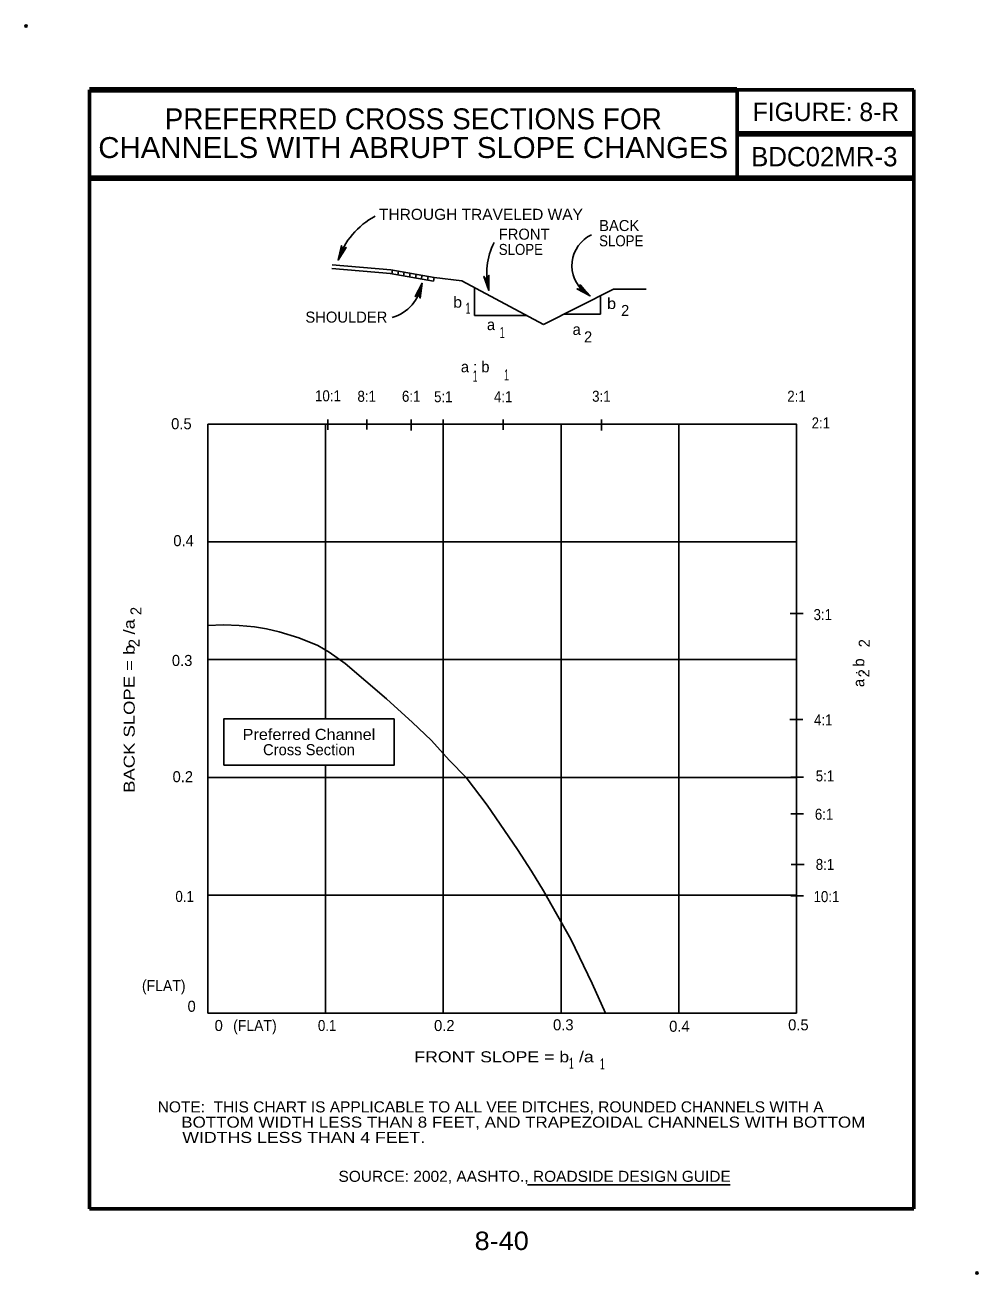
# Model space of a CAD drawing. Extents: x 11.814 to 12.489, y 6.004 to 6.888.
import ezdxf
from ezdxf.enums import TextEntityAlignment as Align

# ---------------------------------------------------------------- set-up
doc = ezdxf.new("R2010")
doc.units = 0
doc.header["$LTSCALE"] = 0.0031
doc.header["$PDMODE"] = 32
doc.header["$PDSIZE"] = 0.00155
doc.layers.add('1', color=7, linetype='Continuous', lineweight=25)
doc.layers.add('24', color=7, linetype='Continuous', lineweight=25)

msp = doc.modelspace()

# ---------------------------------------------------------------- linework, layer by layer
at = {"layer": '1', "lineweight": 60}
for p, q in [((12.443558, 6.842075), (11.859992, 6.842075)), ((11.859992, 6.842075), (11.859992, 6.050092)), ((12.318508, 6.77955), (12.318508, 6.842075)), ((12.443558, 6.050092), (12.443558, 6.842075)), ((12.443558, 6.810817), (12.318508, 6.810817)), ((12.443558, 6.77955), (11.859992, 6.77955)), ((11.859992, 6.050092), (12.443558, 6.050092))]:
    msp.add_line(p, q, dxfattribs=at)
at = {"layer": '1', "lineweight": 90}
for p, q in [((11.859992, 6.842075), (12.318283, 6.842075)), ((12.318575, 6.810833), (12.443558, 6.810833)), ((11.859992, 6.779583), (12.443267, 6.779583))]:
    msp.add_line(p, q, dxfattribs=at)
at = {"layer": '1'}
for p, q in [((12.072992, 6.71195), (12.031467, 6.715592)), ((12.10355, 6.70655), (12.072767, 6.711983)), ((12.073925, 6.711825), (12.074383, 6.7144)), ((12.07815, 6.711075), (12.078608, 6.71365)), ((12.082175, 6.710358), (12.082633, 6.712933)), ((12.086483, 6.709583), (12.086942, 6.712158)), ((12.090742, 6.708825), (12.0912, 6.7114)), ((12.094875, 6.7081), (12.095333, 6.710667)), ((12.099267, 6.707317), (12.099725, 6.709892)), ((12.10355, 6.70655), (12.104008, 6.709125)), ((12.132583, 6.68235), (12.132583, 6.701575)), ((12.231058, 6.700925), (12.181258, 6.676033)), ((12.214333, 6.696117), (12.210717, 6.698633)), ((12.221742, 6.683242), (12.221742, 6.696267)), ((12.231058, 6.700925), (12.254183, 6.700925)), ((12.132583, 6.68235), (12.169058, 6.68235)), ((12.195692, 6.683242), (12.221742, 6.683242)), ((11.943692, 6.60545), (11.943692, 6.188617)), ((12.027058, 6.60545), (12.027058, 6.396808)), ((12.02875, 6.601275), (12.02875, 6.608775)), ((12.056175, 6.601583), (12.056175, 6.608775)), ((12.087667, 6.600958), (12.087667, 6.608775)), ((12.110425, 6.60065), (12.110425, 6.608775)), ((12.110425, 6.60545), (12.110425, 6.188617)), ((12.152817, 6.601275), (12.152817, 6.608775)), ((12.193792, 6.60545), (12.193792, 6.188617)), ((12.22235, 6.600958), (12.22235, 6.608775)), ((12.277158, 6.60545), (12.277158, 6.188617)), ((11.943692, 6.522083), (12.360525, 6.522083)), ((12.356142, 6.4713), (12.365225, 6.4713)), ((11.943692, 6.438717), (12.360525, 6.438717)), ((12.355825, 6.396458), (12.364917, 6.396458)), ((12.027058, 6.364), (12.027058, 6.188617)), ((11.943692, 6.35535), (12.360525, 6.35535)), ((12.35645, 6.355608), (12.365542, 6.355608)), ((12.35645, 6.329483), (12.365542, 6.329483)), ((12.356767, 6.293625), (12.36585, 6.293625)), ((11.943692, 6.271983), (12.360525, 6.271983)), ((12.35645, 6.271483), (12.365542, 6.271483)), ((11.943692, 6.188617), (12.360525, 6.188617)), ((12.17015, 6.067), (12.313483, 6.067))]:
    msp.add_line(p, q, dxfattribs=at)
for points in [[(12.104008, 6.709125), (12.073225, 6.714558), (12.0317, 6.718192)], [(12.104008, 6.709125), (12.123442, 6.7068), (12.181258, 6.676033)], [(11.943692, 6.60545), (12.360525, 6.60545), (12.360525, 6.188617)]]:
    msp.add_lwpolyline(points, dxfattribs=at)
for points in [[(11.943692, 6.188617), (11.943617, 6.462825), (11.954808, 6.463342), (11.965867, 6.462875), (11.976767, 6.461875), (11.985158, 6.460417), (11.9942, 6.45845), (12.008017, 6.454275), (12.021642, 6.44875), (12.0297, 6.444092), (12.041008, 6.435925), (12.070267, 6.410967), (12.088725, 6.394267), (12.10185, 6.381633), (12.114875, 6.367383), (12.126567, 6.355392), (12.141583, 6.33575), (12.163058, 6.304242), (12.172858, 6.288925), (12.181358, 6.275033), (12.200683, 6.240783), (12.215875, 6.209442), (12.225342, 6.188608)], [(11.943692, 6.188617), (11.943617, 6.462825), (11.954808, 6.463342), (11.965867, 6.462875), (11.976767, 6.461875), (11.985158, 6.460417), (11.9942, 6.45845), (12.008017, 6.454275), (12.021642, 6.44875), (12.0297, 6.444092), (12.041008, 6.435925), (12.070267, 6.410967), (12.088725, 6.394267), (12.10185, 6.381633), (12.114875, 6.367383), (12.126567, 6.355392), (12.141583, 6.33575), (12.163058, 6.304242), (12.172858, 6.288925), (12.181358, 6.275033), (12.200683, 6.240783), (12.215875, 6.209442), (12.225342, 6.188608)], [(11.943692, 6.188617), (11.943617, 6.462825), (11.954808, 6.463342), (11.965867, 6.462875), (11.976767, 6.461875), (11.985158, 6.460417), (11.9942, 6.45845), (12.008017, 6.454275), (12.021642, 6.44875), (12.0297, 6.444092), (12.041008, 6.435925), (12.070267, 6.410967), (12.088725, 6.394267), (12.10185, 6.381633), (12.114875, 6.367383), (12.126567, 6.355392), (12.141583, 6.33575), (12.163058, 6.304242), (12.172858, 6.288925), (12.181358, 6.275033), (12.200683, 6.240783), (12.215875, 6.209442), (12.225342, 6.188608)], [(11.955, 6.364), (12.075583, 6.364), (12.075583, 6.396808), (11.955, 6.396808)], [(11.955, 6.364), (12.075583, 6.364), (12.075583, 6.396808), (11.955, 6.396808)], [(11.955, 6.364), (12.075583, 6.364), (12.075583, 6.396808), (11.955, 6.396808)]]:
    msp.add_lwpolyline(points, close=True, dxfattribs=at)
for centre, radius, start, end in [((12.086862, 6.705027), 0.053529, 117.42279, 162.04065), ((12.22559, 6.717598), 0.0241, 115.10644, 231.89061), ((12.189346, 6.712244), 0.048143, 153.1592, 194.61624), ((12.065787, 6.709473), 0.029882, 286.38176, 351.53669)]:
    msp.add_arc(centre, radius, start, end, dxfattribs=at)
for p in [(11.814967, 6.88715), (12.151633, 6.842075), (12.4883, 6.00465)]:
    msp.add_point(p, dxfattribs=at)
at = {"layer": '24'}
for points in [[(12.035942, 6.721533), (12.041633, 6.730433), (12.038983, 6.728842), (12.038242, 6.731783), (12.035942, 6.721533), (12.036192, 6.722183), (12.041392, 6.730217), (12.038883, 6.728675), (12.038217, 6.731342), (12.036308, 6.722533), (12.036483, 6.722833), (12.0409, 6.729733), (12.038867, 6.728625), (12.038275, 6.730883), (12.03655, 6.722983), (12.036633, 6.723325), (12.040508, 6.729342), (12.038858, 6.728542), (12.038225, 6.730325), (12.037017, 6.72425), (12.037242, 6.724792), (12.040067, 6.728958), (12.038842, 6.728433), (12.038283, 6.729783), (12.037333, 6.724867), (12.037575, 6.725367), (12.039583, 6.72855), (12.038642, 6.728167), (12.038283, 6.729158), (12.037742, 6.72585), (12.037983, 6.726317), (12.039233, 6.728208), (12.038633, 6.728067), (12.03835, 6.728833), (12.038042, 6.726583), (12.038917, 6.727792), (12.038475, 6.72775), (12.03835, 6.728492), (12.038133, 6.726942), (12.038725, 6.727733), (12.038275, 6.727483), (12.038283, 6.727983), (12.038375, 6.72745), (12.038517, 6.72765)], [(12.142758, 6.700092), (12.142758, 6.71065), (12.141383, 6.707883), (12.139175, 6.709958), (12.142758, 6.700092), (12.142617, 6.700775), (12.142675, 6.710342), (12.141392, 6.707692), (12.139383, 6.709575), (12.142525, 6.701133), (12.142517, 6.701483), (12.142517, 6.709675), (12.141408, 6.707642), (12.139692, 6.709225), (12.142492, 6.701642), (12.142375, 6.701967), (12.1424, 6.709133), (12.141442, 6.707567), (12.139942, 6.708725), (12.1422, 6.70295), (12.1421, 6.703542), (12.142233, 6.708567), (12.141483, 6.707467), (12.140283, 6.708308), (12.142133, 6.703642), (12.142067, 6.7042), (12.142042, 6.707967), (12.141458, 6.707133), (12.140625, 6.707775), (12.14195, 6.704692), (12.141908, 6.705217), (12.141933, 6.707492), (12.141508, 6.707042), (12.14085, 6.707542), (12.141808, 6.705475), (12.141892, 6.706975), (12.141542, 6.706692), (12.141033, 6.70725), (12.141683, 6.705825), (12.141758, 6.706808), (12.141517, 6.706358), (12.14125, 6.706783), (12.141625, 6.706383), (12.141633, 6.706625)], [(12.095342, 6.705075), (12.090583, 6.69565), (12.093058, 6.6975), (12.094083, 6.69465), (12.095342, 6.705075), (12.095158, 6.704408), (12.090792, 6.695892), (12.093133, 6.697675), (12.094075, 6.695092), (12.095075, 6.704042), (12.094933, 6.703725), (12.091233, 6.696417), (12.09315, 6.697725), (12.093958, 6.695542), (12.094892, 6.703575), (12.094833, 6.703233), (12.091583, 6.69685), (12.09315, 6.6978), (12.093958, 6.6961), (12.09455, 6.702267), (12.094375, 6.7017), (12.091983, 6.697267), (12.093158, 6.697917), (12.093842, 6.696633), (12.0943, 6.701625), (12.094108, 6.701092), (12.092433, 6.697725), (12.093325, 6.6982), (12.093775, 6.697258), (12.093992, 6.7006), (12.093783, 6.700108), (12.092733, 6.6981), (12.093325, 6.698308), (12.093675, 6.697567), (12.093758, 6.699833), (12.093008, 6.69855), (12.09345, 6.698633), (12.09365, 6.697908), (12.093708, 6.699467), (12.0932, 6.698625), (12.093617, 6.698925), (12.093658, 6.698433), (12.093517, 6.69895), (12.0934, 6.698742)], [(12.214333, 6.696117), (12.207325, 6.704017), (12.208133, 6.701033), (12.2051, 6.701125), (12.214333, 6.696117), (12.213775, 6.696533), (12.207475, 6.703733), (12.208267, 6.7009), (12.205525, 6.700975), (12.213467, 6.696742), (12.213225, 6.696992), (12.2078, 6.703125), (12.208308, 6.700867), (12.205975, 6.700917), (12.2131, 6.697092), (12.2128, 6.697267), (12.208067, 6.702642), (12.208383, 6.700833), (12.2065, 6.700708), (12.212008, 6.697892), (12.21155, 6.69825), (12.208317, 6.702117), (12.208492, 6.700792), (12.207033, 6.700625), (12.2115, 6.698358), (12.211092, 6.698733), (12.208575, 6.701533), (12.208683, 6.700525), (12.207642, 6.70045), (12.210667, 6.699025), (12.210292, 6.699392), (12.208808, 6.701108), (12.208783, 6.700483), (12.207967, 6.700425), (12.21005, 6.699517), (12.209125, 6.700692), (12.209042, 6.70025), (12.208292, 6.700333), (12.209725, 6.6997), (12.209125, 6.700483), (12.209242, 6.699983), (12.208767, 6.700125), (12.209308, 6.700075), (12.209158, 6.700258)]]:
    msp.add_lwpolyline(points, dxfattribs=at)

# ---------------------------------------------------------------- texts
at = {"layer": '1'}
for s, height, p in [('PREFERRED CROSS SECTIONS FOR', 0.01481, (12.089133, 6.814075)), ('FIGURE: 8-R', 0.01303, (12.38135, 6.819933)), ('BDC02MR-3', 0.01368, (12.380204, 6.787892)), ('Cross Section', 0.007817, (12.015288, 6.371092))]:
    msp.add_text(s, height=height, dxfattribs=at).set_placement(p, align=Align.CENTER)
for s, height, width, p in [('CHANNELS WITH ABRUPT SLOPE CHANGES', 0.01481, 1.05, (12.089133, 6.793758)), ('10:1', 0.007808, 0.9, (12.02875, 6.621542)), ('8:1', 0.007808, 0.9, (12.056175, 6.621225)), ('6:1', 0.007808, 0.9, (12.087667, 6.621225)), ('5:1', 0.007808, 0.9, (12.110425, 6.620917)), ('4:1', 0.007808, 0.9, (12.152817, 6.620917)), ('3:1', 0.007808, 0.9, (12.22235, 6.621242)), ('2:1', 0.007808, 0.9, (12.360525, 6.621242)), ('Preferred Channel', 0.007817, 1.1, (12.015288, 6.381908)), ('8-40', 0.01303, 1.1, (12.151775, 6.020858))]:
    msp.add_text(s, height=height, dxfattribs=dict(at, width=width)).set_placement(p, align=Align.CENTER)
for s, width, p in [('THROUGH TRAVELED WAY', 1.05, (12.064925, 6.75)), ('SLOPE', 0.9, (12.220775, 6.731267)), ('SLOPE', 0.9, (12.149683, 6.72515)), ('b', 1.1, (12.117358, 6.68785)), ('b', 1.1, (12.226375, 6.6869)), ('1', 0.6, (12.126158, 6.683508)), ('1', 0.6, (12.150383, 6.66635)), ('1', 0.6, (12.131217, 6.6354)), ('1', 0.6, (12.153467, 6.636308)), ('2:1', 0.9, (12.37125, 6.6024)), ('3:1', 0.9, (12.372617, 6.4667)), ('4:1', 0.9, (12.372917, 6.392167)), ('5:1', 0.9, (12.374167, 6.352558)), ('6:1', 0.9, (12.373533, 6.325433)), ('8:1', 0.9, (12.374167, 6.289875)), ('0.1', 0.9, (11.920733, 6.267208)), ('10:1', 0.9, (12.372608, 6.267117)), ('(FLAT)', 0.95, (11.897025, 6.204125)), ('(FLAT)', 0.95, (11.961608, 6.175867)), ('0.1', 0.9, (12.021633, 6.175867)), ('FRONT SLOPE = b  /a', 1.2, (12.089883, 6.153708)), ('1', 0.6, (12.199342, 6.149117)), ('1', 0.6, (12.221333, 6.148675)), ('NOTE:  THIS CHART IS APPLICABLE TO ALL VEE DITCHES, ROUNDED CHANNELS WITH A', 1.05, (11.9082, 6.118275)), ('     BOTTOM WIDTH LESS THAN 8 FEET, AND TRAPEZOIDAL CHANNELS WITH BOTTOM', 1.15, (11.9082, 6.107467)), ('     WIDTHS LESS THAN 4 FEET.', 1.2, (11.9082, 6.096658)), ('SOURCE: 2002, AASHTO., ROADSIDE DESIGN GUIDE', 1.05, (12.036192, 6.069125))]:
    msp.add_text(s, height=0.007808, dxfattribs=dict(at, width=width)).set_placement(p)
for s, p in [('BACK', (12.220775, 6.742075)), ('FRONT', (12.149683, 6.735958)), ('SHOULDER', (12.012775, 6.677258)), ('2', (12.236283, 6.681958)), ('a', (12.141283, 6.671967)), ('a', (12.201967, 6.668542)), ('2', (12.210067, 6.663242)), ('a : b', (12.122817, 6.642083)), ('0.5', (11.917717, 6.601792)), ('0.4', (11.919225, 6.519033)), ('0.3', (11.918225, 6.43425)), ('0.2', (11.918717, 6.351983)), ('0', (11.929317, 6.189483)), ('0', (11.948483, 6.175867)), ('0.2', (12.103875, 6.17585)), ('0.3', (12.188133, 6.176367)), ('0.4', (12.270367, 6.17535)), ('0.5', (12.354617, 6.176342))]:
    msp.add_text(s, height=0.007808, dxfattribs=at).set_placement(p)
for s, p in [('2', (11.896708, 6.47025)), ('2', (11.895375, 6.44755)), ('2', (12.412425, 6.447442)), ('a : b', (12.40855, 6.419283)), ('2', (12.412175, 6.426183))]:
    msp.add_text(s, height=0.007808, rotation=90, dxfattribs=at).set_placement(p)
at = {"layer": '1', "width": 1.25}
msp.add_text('BACK SLOPE = b  /a', height=0.007808, rotation=90, dxfattribs=at).set_placement((11.8919, 6.344458))

doc.saveas('drawing.dxf')
